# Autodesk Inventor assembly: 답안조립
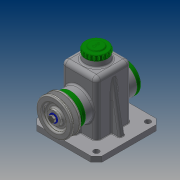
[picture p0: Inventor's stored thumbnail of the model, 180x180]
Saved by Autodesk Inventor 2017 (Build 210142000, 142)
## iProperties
Part Number: 답안조립
Material: 일반
Document SubType Name: Assembly
Designer: 20
Author: 20
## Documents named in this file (14)
- C:\Users\20\Desktop\470818V1010\답안조립.iam
- C:\Users\20\Desktop\470818V1010\본체.ipt
- C:\Users\20\Desktop\470818V1010\앞커버.ipt
- C:\Users\20\Desktop\470818V1010\뒤커버.ipt
- C:\Users\20\Desktop\470818V1010\베어링 15 x 35 x 11.ipt
- C:\Users\20\Desktop\470818V1010\축.ipt
- C:\Users\20\Desktop\470818V1010\멈춤링 15 x 1.ipt
- C:\Users\20\Desktop\470818V1010\키 5 x 5 x 14.ipt
- C:\Users\20\Desktop\470818V1010\V-벨트풀리.ipt
- C:\Users\20\Desktop\470818V1010\와셔.ipt
- C:\Users\20\Desktop\470818V1010\볼트 M6 x 12.ipt
- C:\Users\20\Desktop\470818V1010\볼트 M4 x 10.ipt
- C:\Users\20\Desktop\470818V1010\상부캡.ipt
- C:\Users\20\Desktop\470818V1010\오일실 15 25 7.ipt
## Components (1 placed, 1 different names)
1. V-벨트풀리:1
